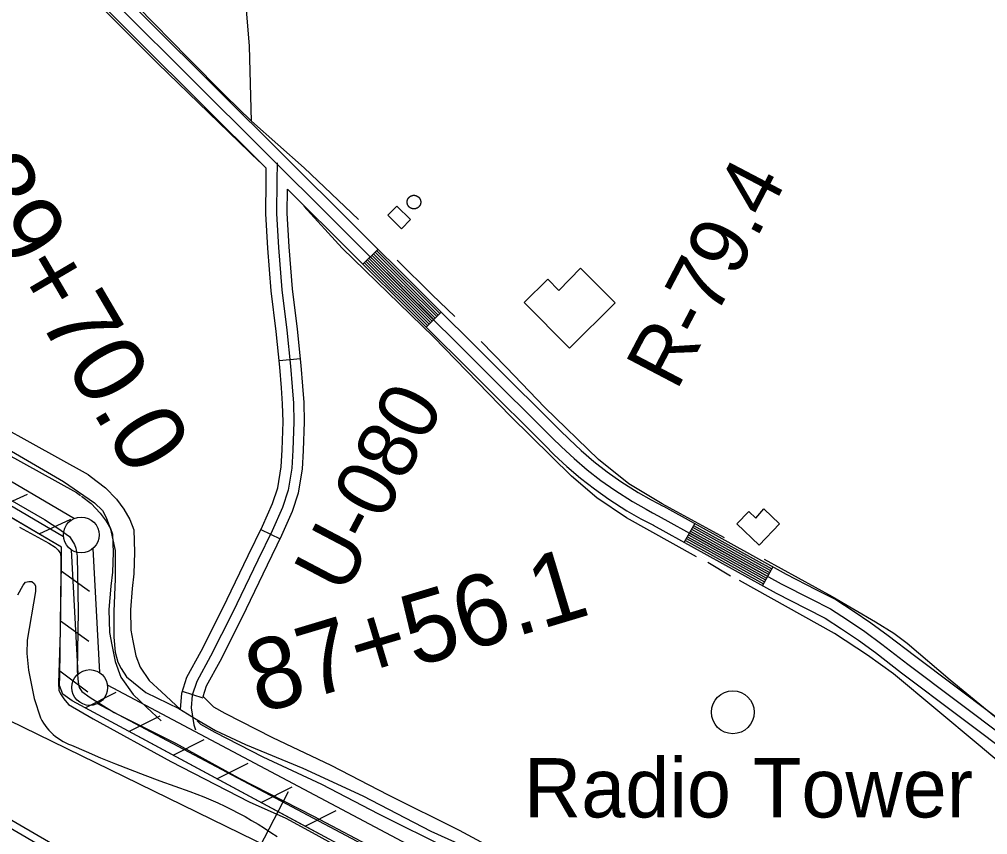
# Model space of a CAD drawing. Extents: x 3715084 to 3753216, y 488173 to 513963.
# Drawn here: x 3720352 to 3721709, y 504207 to 505348 of the extents above; entities that cross this region are included whole.
import ezdxf

# ---------------------------------------------------------------- set-up
doc = ezdxf.new("R2010")
doc.units = 0
for name, color, linetype in [('V-BLDG-OTLN', 7, 'Continuous'), ('V-DOMW-TANK', 7, 'Continuous'), ('V-FLOD-BASE', 7, 'Continuous'), ('V-LEVE-TOET', 7, 'Continuous'), ('V-RIVR-RANG', 7, 'Continuous'), ('V-RIVR-RANG-IDEN', 7, 'Continuous'), ('V-ROAD-CNTR', 7, 'Continuous'), ('V-RRAP-FSHR', 7, 'Continuous'), ('V-SITE-VEGE', 7, 'Continuous'), ('V-SURV-IDEN', 7, 'Continuous'), ('V-SURV-LINE', 7, 'Continuous'), ('V-TOPO-DPTH', 7, 'Continuous'), ('V-TOPO-MINR', 7, 'Continuous'), ('V-TOPO-SHOR', 7, 'Continuous'), ('V-TOPO-TOWR', 7, 'Continuous'), ('V-TOPO-TOWR-IDEN', 7, 'Continuous'), ('V-TOPO-WATR', 7, 'Continuous')]:
    doc.layers.add(name, color=color, linetype=linetype)

msp = doc.modelspace()

# ---------------------------------------------------------------- linework, layer by layer
at = {"layer": 'V-BLDG-OTLN'}
for points in [[(3720880.9, 505086.5), (3720900, 505067.6), (3720887.4, 505054.9), (3720868.4, 505073.7)], [(3721138.3, 504999.6), (3721186.6, 504950.9), (3721122.8, 504887.7), (3721059.4, 504951.7), (3721092.3, 504984.2), (3721107.9, 504968.4)], [(3721395, 504662.5), (3721416.8, 504641.5), (3721388.4, 504612), (3721357.4, 504641.9), (3721374, 504659.1), (3721383.7, 504649.8)]]:
    msp.add_lwpolyline(points, close=True, dxfattribs=at)
at = {"layer": 'V-DOMW-TANK'}
for points in [[(3720896, 505095.7), (3720896.1, 505095.8), (3720896.1, 505096), (3720896.2, 505096.1), (3720896.3, 505096.3), (3720896.3, 505096.4), (3720896.4, 505096.6), (3720896.5, 505096.7), (3720896.6, 505096.9), (3720896.7, 505097), (3720896.7, 505097.2), (3720896.8, 505097.3), (3720896.9, 505097.4), (3720897, 505097.6), (3720897.1, 505097.7), (3720897.2, 505097.8), (3720897.3, 505098), (3720897.4, 505098.1), (3720897.5, 505098.2), (3720897.6, 505098.4), (3720897.7, 505098.5), (3720897.8, 505098.6), (3720898, 505098.7), (3720898.1, 505098.8), (3720898.2, 505099), (3720898.3, 505099.1), (3720898.4, 505099.2), (3720898.6, 505099.3), (3720898.7, 505099.4), (3720898.8, 505099.5), (3720899, 505099.6), (3720899.1, 505099.7), (3720899.2, 505099.8), (3720899.4, 505099.9), (3720899.5, 505100), (3720899.6, 505100.1), (3720899.8, 505100.2), (3720899.9, 505100.3), (3720900.1, 505100.4), (3720900.2, 505100.4), (3720900.3, 505100.5), (3720900.5, 505100.6), (3720900.6, 505100.7), (3720900.8, 505100.8), (3720900.9, 505100.8), (3720901.1, 505100.9), (3720901.2, 505100.9), (3720901.4, 505101), (3720901.6, 505101.1), (3720901.7, 505101.1), (3720901.9, 505101.2), (3720902, 505101.2), (3720902.2, 505101.3), (3720902.3, 505101.3), (3720902.5, 505101.4), (3720902.7, 505101.4), (3720902.8, 505101.4), (3720903, 505101.5), (3720903.2, 505101.5), (3720903.3, 505101.5), (3720903.5, 505101.6), (3720903.7, 505101.6), (3720903.8, 505101.6), (3720904, 505101.6), (3720904.1, 505101.6), (3720904.3, 505101.6), (3720904.5, 505101.6), (3720904.6, 505101.6), (3720904.8, 505101.6), (3720905, 505101.6), (3720905.1, 505101.6), (3720905.3, 505101.6), (3720905.5, 505101.6), (3720905.6, 505101.6), (3720905.8, 505101.6), (3720906, 505101.6), (3720906.1, 505101.6), (3720906.3, 505101.5), (3720906.5, 505101.5), (3720906.6, 505101.5), (3720906.8, 505101.4), (3720907, 505101.4), (3720907.1, 505101.4), (3720907.3, 505101.3), (3720907.4, 505101.3), (3720907.6, 505101.2), (3720907.8, 505101.2), (3720907.9, 505101.1), (3720908.1, 505101.1), (3720908.2, 505101), (3720908.4, 505101), (3720908.5, 505100.9), (3720908.7, 505100.8), (3720908.8, 505100.8), (3720909, 505100.7), (3720909.1, 505100.6), (3720909.3, 505100.5), (3720909.4, 505100.5), (3720909.6, 505100.4), (3720909.7, 505100.3), (3720909.9, 505100.2)], [(3720902.9, 505082.8), (3720902.7, 505082.8), (3720902.5, 505082.9), (3720902.4, 505082.9), (3720902.2, 505083), (3720902.1, 505083), (3720901.9, 505083.1), (3720901.7, 505083.1), (3720901.6, 505083.2), (3720901.4, 505083.2), (3720901.3, 505083.3), (3720901.1, 505083.3), (3720901, 505083.4), (3720900.8, 505083.5), (3720900.7, 505083.6), (3720900.5, 505083.6), (3720900.4, 505083.7), (3720900.2, 505083.8), (3720900.1, 505083.9), (3720899.9, 505084), (3720899.8, 505084), (3720899.6, 505084.1), (3720899.5, 505084.2), (3720899.4, 505084.3), (3720899.2, 505084.4), (3720899.1, 505084.5), (3720899, 505084.6), (3720898.8, 505084.7), (3720898.7, 505084.8), (3720898.6, 505084.9), (3720898.5, 505085), (3720898.3, 505085.1), (3720898.2, 505085.3), (3720898.1, 505085.4), (3720898, 505085.5), (3720897.9, 505085.6), (3720897.8, 505085.7), (3720897.6, 505085.9), (3720897.5, 505086), (3720897.4, 505086.1), (3720897.3, 505086.2), (3720897.2, 505086.4), (3720897.1, 505086.5), (3720897, 505086.6), (3720896.9, 505086.8), (3720896.8, 505086.9), (3720896.8, 505087.1), (3720896.7, 505087.2), (3720896.6, 505087.4), (3720896.5, 505087.5), (3720896.4, 505087.6), (3720896.3, 505087.8), (3720896.3, 505087.9), (3720896.2, 505088.1), (3720896.1, 505088.2), (3720896.1, 505088.4), (3720896, 505088.5), (3720895.9, 505088.7), (3720895.9, 505088.9), (3720895.8, 505089), (3720895.8, 505089.2), (3720895.7, 505089.3), (3720895.7, 505089.5), (3720895.6, 505089.6), (3720895.6, 505089.8), (3720895.5, 505090), (3720895.5, 505090.1), (3720895.5, 505090.3), (3720895.4, 505090.5), (3720895.4, 505090.6), (3720895.4, 505090.8), (3720895.4, 505091), (3720895.4, 505091.1), (3720895.3, 505091.3), (3720895.3, 505091.4), (3720895.3, 505091.6), (3720895.3, 505091.8), (3720895.3, 505091.9), (3720895.3, 505092.1), (3720895.3, 505092.3), (3720895.3, 505092.4), (3720895.3, 505092.6), (3720895.3, 505092.8), (3720895.3, 505092.9), (3720895.4, 505093.1), (3720895.4, 505093.3), (3720895.4, 505093.4), (3720895.4, 505093.6), (3720895.4, 505093.8), (3720895.5, 505093.9), (3720895.5, 505094.1), (3720895.5, 505094.3), (3720895.6, 505094.4), (3720895.6, 505094.6), (3720895.7, 505094.7), (3720895.7, 505094.9), (3720895.8, 505095.1), (3720895.8, 505095.2), (3720895.9, 505095.4), (3720895.9, 505095.5), (3720896, 505095.7)], [(3720914.3, 505091.8), (3720914.3, 505091.6), (3720914.3, 505091.5), (3720914.3, 505091.3), (3720914.3, 505091.1), (3720914.3, 505091), (3720914.3, 505090.8), (3720914.2, 505090.6), (3720914.2, 505090.5), (3720914.2, 505090.3), (3720914.1, 505090.2), (3720914.1, 505090), (3720914.1, 505089.8), (3720914, 505089.7), (3720914, 505089.5), (3720913.9, 505089.4), (3720913.9, 505089.2), (3720913.8, 505089), (3720913.8, 505088.9), (3720913.7, 505088.7), (3720913.7, 505088.6), (3720913.6, 505088.4), (3720913.5, 505088.3), (3720913.5, 505088.1), (3720913.4, 505088), (3720913.3, 505087.8), (3720913.2, 505087.7), (3720913.2, 505087.5), (3720913.1, 505087.4), (3720913, 505087.2), (3720912.9, 505087.1), (3720912.8, 505086.9), (3720912.7, 505086.8), (3720912.6, 505086.7), (3720912.5, 505086.5), (3720912.4, 505086.4), (3720912.3, 505086.3), (3720912.2, 505086.1), (3720912.1, 505086), (3720912, 505085.9), (3720911.9, 505085.8), (3720911.8, 505085.6), (3720911.7, 505085.5), (3720911.6, 505085.4), (3720911.5, 505085.3), (3720911.3, 505085.2), (3720911.2, 505085.1), (3720911.1, 505084.9), (3720911, 505084.8), (3720910.8, 505084.7), (3720910.7, 505084.6), (3720910.6, 505084.5), (3720910.4, 505084.4), (3720910.3, 505084.3), (3720910.2, 505084.2), (3720910, 505084.1), (3720909.9, 505084.1), (3720909.7, 505084), (3720909.6, 505083.9), (3720909.5, 505083.8), (3720909.3, 505083.7), (3720909.2, 505083.6), (3720909, 505083.6), (3720908.9, 505083.5), (3720908.7, 505083.4), (3720908.6, 505083.4), (3720908.4, 505083.3), (3720908.3, 505083.2), (3720908.1, 505083.2), (3720907.9, 505083.1), (3720907.8, 505083.1), (3720907.6, 505083), (3720907.5, 505083), (3720907.3, 505082.9), (3720907.1, 505082.9), (3720907, 505082.8), (3720906.8, 505082.8), (3720906.7, 505082.8), (3720906.5, 505082.7), (3720906.3, 505082.7), (3720906.2, 505082.7), (3720906, 505082.7), (3720905.8, 505082.7), (3720905.7, 505082.6), (3720905.5, 505082.6), (3720905.3, 505082.6), (3720905.2, 505082.6), (3720905, 505082.6), (3720904.8, 505082.6), (3720904.7, 505082.6), (3720904.5, 505082.6), (3720904.3, 505082.6), (3720904.2, 505082.6), (3720904, 505082.6), (3720903.8, 505082.7), (3720903.7, 505082.7), (3720903.5, 505082.7), (3720903.3, 505082.7), (3720903.2, 505082.7), (3720903, 505082.8), (3720902.9, 505082.8)], [(3720909.9, 505100.2), (3720910, 505100.1), (3720910.1, 505100), (3720910.3, 505099.9), (3720910.4, 505099.8), (3720910.5, 505099.7), (3720910.7, 505099.6), (3720910.8, 505099.5), (3720910.9, 505099.4), (3720911.1, 505099.3), (3720911.2, 505099.2), (3720911.3, 505099.1), (3720911.4, 505099), (3720911.6, 505098.9), (3720911.7, 505098.7), (3720911.8, 505098.6), (3720911.9, 505098.5), (3720912, 505098.4), (3720912.1, 505098.3), (3720912.2, 505098.1), (3720912.3, 505098), (3720912.4, 505097.9), (3720912.5, 505097.7), (3720912.6, 505097.6), (3720912.7, 505097.5), (3720912.8, 505097.3), (3720912.9, 505097.2), (3720913, 505097), (3720913.1, 505096.9), (3720913.1, 505096.8), (3720913.2, 505096.6), (3720913.3, 505096.5), (3720913.4, 505096.3), (3720913.5, 505096.2), (3720913.5, 505096), (3720913.6, 505095.9), (3720913.7, 505095.7), (3720913.7, 505095.5), (3720913.8, 505095.4), (3720913.8, 505095.2), (3720913.9, 505095.1), (3720913.9, 505094.9), (3720914, 505094.8), (3720914, 505094.6), (3720914.1, 505094.4), (3720914.1, 505094.3), (3720914.1, 505094.1), (3720914.2, 505094), (3720914.2, 505093.8), (3720914.2, 505093.6), (3720914.3, 505093.5), (3720914.3, 505093.3), (3720914.3, 505093.1), (3720914.3, 505093), (3720914.3, 505092.8), (3720914.3, 505092.6), (3720914.3, 505092.5), (3720914.4, 505092.3), (3720914.4, 505092.1), (3720914.4, 505092), (3720914.3, 505091.8)]]:
    msp.add_lwpolyline(points, dxfattribs=at)
at = {"layer": 'V-FLOD-BASE'}
msp.add_lwpolyline([(3720298.4, 504698.8), (3720387, 504647.6), (3720408.5, 504633.6), (3720417.7, 504627.4), (3720422.3, 504623.9), (3720425.5, 504619), (3720429.3, 504612.7), (3720431.2, 504607.4), (3720433.2, 504596.6), (3720434.2, 504519.3), (3720433.1, 504435.7), (3720434.3, 504419.9), (3720435.8, 504412.7), (3720439.5, 504406.9), (3720451, 504398.5), (3720484.8, 504377.5), (3720570.6, 504334.4), (3720659.1, 504285.9), (3720764.1, 504232.4), (3720856.3, 504184)], dxfattribs=at)
at = {"layer": 'V-LEVE-TOET'}
for points in [[(3720306.7, 504763.1), (3720414, 504701), (3720457.5, 504671.1), (3720468.6, 504660.5), (3720473.7, 504650.6), (3720479.5, 504634), (3720486.3, 504604.3), (3720486.2, 504564.6), (3720484.4, 504518.9), (3720484.6, 504482.8), (3720486.3, 504462), (3720489.8, 504448.1), (3720494.5, 504439.1), (3720501.9, 504427.5), (3720529.4, 504405.5), (3720575.5, 504383.3), (3720599.6, 504368.1), (3720627, 504352.3), (3720669, 504332.8), (3720749.1, 504299.5), (3720833, 504260.9), (3720928.4, 504211.2), (3721018.6, 504171)], [(3720352, 504637), (3720393.1, 504614.8), (3720402.2, 504609.1), (3720406.4, 504604.6), (3720409.6, 504600.2), (3720410.8, 504588), (3720409, 504490.4), (3720406.8, 504418.5), (3720407.4, 504409), (3720409.8, 504403.6), (3720414.4, 504396.5), (3720420.9, 504388.9), (3720455.6, 504368.8), (3720564.3, 504309), (3720673.8, 504252.3), (3720725.3, 504229.8), (3720762.3, 504209.3), (3720849.5, 504161.3)]]:
    msp.add_lwpolyline(points, dxfattribs=at)
at = {"layer": 'V-RIVR-RANG'}
msp.add_line((3720728.8, 504266.5), (3720358.7, 503557.2), dxfattribs=at)
at = {"layer": 'V-ROAD-CNTR'}
for p, q in [((3720854.5, 505026.3), (3720833.3, 505005.1)), ((3720943.1, 504938.2), (3720922, 504916.9)), ((3720715.9, 504870.2), (3720745.8, 504873.1)), ((3721298.2, 504642), (3721283.6, 504615.8)), ((3720690.4, 504633.8), (3720717.4, 504620.7)), ((3721407.5, 504581.5), (3721393, 504555.2)), ((3720580.3, 504407.3), (3720608.9, 504398.1))]:
    msp.add_line(p, q, dxfattribs=at)
for points in [[(3719189.4, 506660.7), (3719987.9, 505866.9), (3721098.7, 504762.3), (3721111.7, 504749.3), (3721129.2, 504733), (3721147.4, 504717.5), (3721166.7, 504702.5), (3721186.3, 504688.6), (3721211, 504672.9), (3721230.2, 504662), (3721239.2, 504657.2), (3721247.2, 504653.1)], [(3719529.4, 506301.6), (3719977.3, 505856.2), (3720697.9, 505139.7)], [(3720145.3, 505731.5), (3721109.3, 504772.9), (3721122.1, 504760.1), (3721139.2, 504744.2), (3721156.9, 504729.1), (3721175.6, 504714.6), (3721194.7, 504701.1), (3721218.8, 504685.7), (3721237.4, 504675.1), (3721246.1, 504670.5), (3721254, 504666.4)], [(3720713.1, 505147.3), (3720712.6, 505121.8), (3720712.3, 505076.2), (3720714.9, 505028.6), (3720719.9, 504969.3), (3720726.9, 504912.6), (3720731.8, 504862.2), (3720734.1, 504833.3), (3720735.9, 504810.6), (3720736.4, 504784.6), (3720735, 504744.8), (3720733.8, 504719.7), (3720728.6, 504688.7), (3720720.7, 504664.7), (3720706.2, 504632.1), (3720686.1, 504590.8), (3720650.5, 504517), (3720620, 504456.3), (3720600.5, 504421), (3720594.3, 504401.9), (3720592.9, 504384.1), (3720596.5, 504360.3), (3720598.8, 504353.4)], [(3720577.7, 504381.5), (3720579.5, 504404.8), (3720586.7, 504427), (3720606.8, 504463.3), (3720637.1, 504523.6), (3720672.6, 504597.3), (3720692.6, 504638.4), (3720706.6, 504670.1), (3720714, 504692.3), (3720718.9, 504721.3), (3720720, 504745.4), (3720721.4, 504784.7), (3720720.9, 504809.9), (3720719.1, 504832.1), (3720716.9, 504860.9), (3720712, 504910.9), (3720705, 504967.8), (3720700, 505027.5), (3720697.3, 505075.8), (3720697.6, 505122), (3720697.9, 505139.7)], [(3720609.4, 504399.8), (3720614.3, 504415), (3720633.3, 504449.3), (3720664, 504510.4), (3720699.6, 504584.3), (3720719.8, 504625.8), (3720734.7, 504659.3), (3720743.2, 504685.1), (3720748.8, 504718.1), (3720750, 504744.2), (3720751.4, 504784.5), (3720750.8, 504811.4), (3720749, 504834.4), (3720746.7, 504863.5), (3720741.8, 504914.2), (3720734.9, 504970.9), (3720729.9, 505029.6), (3720727.3, 505076.6), (3720727.5, 505110.3)], [(3720727.5, 505110.3), (3721088.1, 504751.7), (3721101.3, 504738.5), (3721119.2, 504721.8), (3721138, 504705.8), (3721157.8, 504690.5), (3721177.9, 504676.2), (3721203.3, 504660.1), (3721222.9, 504648.8), (3721232.2, 504643.9), (3721240.3, 504639.7)], [(3720850.3, 505022.1), (3720938.9, 504933.9)], [(3720852.4, 505024.2), (3720941, 504936.1)], [(3720835.5, 505007.2), (3720924.1, 504919)], [(3720837.6, 505009.3), (3720926.2, 504921.2)], [(3720839.7, 505011.4), (3720928.3, 504923.3)], [(3720841.8, 505013.6), (3720930.4, 504925.4)], [(3720843.9, 505015.7), (3720932.6, 504927.6)], [(3720846, 505017.8), (3720934.7, 504929.7)], [(3720848.1, 505019.9), (3720936.8, 504931.8)], [(3720052.4, 504938), (3720245.9, 504822.8), (3720448.5, 504710.8), (3720451.4, 504708.6)], [(3720026.4, 504918.6), (3720230.9, 504796.8), (3720432, 504685.6), (3720437.6, 504681.3)], [(3720451.4, 504708.6), (3720472.6, 504692.3), (3720487.9, 504676.1), (3720498.6, 504662.4), (3720507, 504647.7), (3720512.5, 504633.1), (3720513.5, 504601.8), (3720512.6, 504571.7), (3720510, 504551.3), (3720507.6, 504521.1), (3720508.4, 504492.6), (3720511.1, 504477.7), (3720515.2, 504457), (3720521.1, 504441.1), (3720534.1, 504422.3), (3720551, 504406.5), (3720577.7, 504381.5)], [(3720438.9, 504680.3), (3720452.4, 504670), (3720465.1, 504656.5), (3720473.6, 504645.6), (3720479.7, 504635), (3720482.6, 504627.2), (3720483.5, 504601.7), (3720482.7, 504574.1), (3720480.2, 504554.4), (3720477.5, 504521.9), (3720478.5, 504489.5), (3720481.6, 504472.1), (3720486.3, 504448.7), (3720494.3, 504427.2), (3720511.3, 504402.6), (3720530.5, 504384.6), (3720550.6, 504365.8)], [(3721254.4, 504666.2), (3721426.2, 504571.2), (3721467.9, 504549.8), (3721495.7, 504535.7), (3721520.4, 504519.8), (3721544.9, 504503.1), (3721569.4, 504485.3), (3721606.1, 504457.1), (3722648.1, 503674.3)], [(3721247.2, 504653.1), (3721419.1, 504557.9), (3721461.1, 504536.5), (3721488.2, 504522.7), (3721512.1, 504507.3), (3721536.3, 504490.9), (3721560.4, 504473.3), (3721597, 504445.1), (3722971.8, 503412.3)], [(3721239.9, 504640), (3721412.1, 504544.7), (3721454.3, 504523.1), (3721480.8, 504509.6), (3721503.9, 504494.8), (3721527.6, 504478.6), (3721551.5, 504461.3), (3721587.9, 504433.2), (3722963.1, 503400.1)], [(3721290.9, 504628.9), (3721400.3, 504568.3)], [(3721292.4, 504631.5), (3721401.7, 504571)], [(3721293.8, 504634.1), (3721403.2, 504573.6)], [(3721295.3, 504636.8), (3721404.6, 504576.2)], [(3721296.7, 504639.4), (3721406.1, 504578.8)], [(3721285.1, 504618.4), (3721394.5, 504557.8)], [(3721286.5, 504621), (3721395.9, 504560.5)], [(3721288, 504623.6), (3721397.4, 504563.1)], [(3721289.4, 504626.3), (3721398.8, 504565.7)], [(3720609.4, 504399.8), (3720624.1, 504385.5), (3720640, 504376.5), (3720706.5, 504342.3), (3720788.4, 504304), (3720868.6, 504262.2), (3720968.4, 504213), (3721162.4, 504108.3), (3721455.4, 503950.6), (3721693.3, 503826.5), (3721910.2, 503710.8), (3722158.7, 503578.4), (3722275.3, 503519.1), (3722449.8, 503437.7), (3722572.5, 503385.9), (3722717.5, 503324.9), (3722918.2, 503240.7), (3723155.5, 503141.6), (3723379.3, 503050.7), (3723688.8, 502924.5), (3723919.3, 502828.6)], [(3720601.1, 504366), (3720605.9, 504361.3), (3720625.8, 504350.1), (3720693.3, 504315.4), (3720775.1, 504277.1), (3720855.1, 504235.5), (3720954.6, 504186.4), (3721148.2, 504081.9), (3721441.3, 503924.1), (3721679.3, 503800), (3721896.1, 503684.3), (3722144.8, 503551.8), (3722262.2, 503492.2), (3722437.7, 503410.3), (3722560.8, 503358.3), (3722705.8, 503297.2), (3722906.7, 503213), (3723144.1, 503113.8), (3723368, 503022.9), (3723677.4, 502896.7), (3723907.8, 502800.8)]]:
    msp.add_lwpolyline(points, dxfattribs=at)
at = {"layer": 'V-RRAP-FSHR'}
for p, q in [((3720319.2, 504663.1), (3720363.6, 504683.4)), ((3720379.6, 504627.7), (3720424, 504648)), ((3720410.7, 504575.8), (3720450.3, 504547.2)), ((3720409.8, 504505.8), (3720449.4, 504477.2)), ((3720408.9, 504435.8), (3720448.1, 504406.6)), ((3720444, 504384.2), (3720487.6, 504406.2)), ((3720505.6, 504351.1), (3720549.2, 504373)), ((3720567.3, 504317.9), (3720610.9, 504339.9)), ((3720628.9, 504284.7), (3720672.5, 504306.7)), ((3720690.6, 504251.6), (3720734.2, 504273.5)), ((3720752.2, 504218.4), (3720795.8, 504240.4))]:
    msp.add_line(p, q, dxfattribs=at)
for points in [[(3726789.8, 501978.8), (3725909.9, 502250.2), (3725810, 502279.5), (3725043.4, 502441), (3724981.8, 502452.9), (3724595, 502499.9), (3724237.6, 502584.4), (3723904.7, 502725.9), (3723011.3, 503091.7), (3722299.3, 503386.1), (3720426.2, 504393.8), (3720412.7, 504403.1), (3720408.3, 504415.1), (3720408.7, 504428.5), (3720411.2, 504609.1), (3719265.5, 505280.9), (3719251.6, 505287.3), (3719232.5, 505288), (3719209.2, 505282.4)], [(3723870.2, 502642), (3719362.2, 504842.3), (3719213.6, 504918.2)], [(3720771.9, 504207.8), (3720426.2, 504393.8), (3720412.7, 504403.1), (3720408.3, 504415.1), (3720408.7, 504428.5), (3720411.2, 504609.1), (3720241, 504708.9)]]:
    msp.add_lwpolyline(points, dxfattribs=at)
at = {"layer": 'V-SITE-VEGE'}
for points in [[(3720350, 504542.1), (3720357.3, 504555.6), (3720360.8, 504560.1)], [(3720360.8, 504560.1), (3720365.2, 504561.1), (3720369.3, 504560.8), (3720372.9, 504558.1), (3720374.7, 504555.1), (3720374.4, 504547), (3720362.8, 504479), (3720362.3, 504460.2), (3720364.9, 504436.6), (3720372.8, 504397.1), (3720381.4, 504370), (3720383.4, 504366.3), (3720385.7, 504362.7), (3720388.1, 504359.3), (3720390.7, 504355.9), (3720393.5, 504352.7), (3720396.5, 504349.7), (3720399.6, 504346.8), (3720402.8, 504344.1), (3720406.2, 504341.5), (3720409.8, 504339.1), (3720413.4, 504337), (3720417.1, 504335), (3720421, 504333.2), (3720424.9, 504331.6), (3720445.4, 504322.8), (3720465.9, 504314.2), (3720486.5, 504305.8), (3720507.2, 504297.6), (3720528, 504289.7), (3720548.8, 504281.9), (3720569.8, 504274.3), (3720590.8, 504267), (3720600.7, 504263.2), (3720610.6, 504259.3), (3720620.4, 504255.2), (3720630.2, 504250.9), (3720639.8, 504246.4), (3720649.3, 504241.7), (3720658.8, 504236.8), (3720668.2, 504231.7), (3720677.4, 504226.5), (3720686.6, 504221.1), (3720695.6, 504215.5), (3720704.5, 504209.7), (3720713.3, 504203.7)]]:
    msp.add_lwpolyline(points, dxfattribs=at)
at = {"layer": 'V-SURV-LINE'}
for points in [[(3719281.5, 505324.1), (3720429.1, 504649.2)], [(3720413.9, 504623.3), (3719266.3, 505298.3)], [(3720434.5, 504431.7), (3720424.9, 504605.4)], [(3720454.8, 504607), (3720464.4, 504433.3)], [(3720475.2, 504416.4), (3722364, 503414.7)], [(3722349.9, 503388.2), (3720461.2, 504389.9)]]:
    msp.add_lwpolyline(points, dxfattribs=at)
for centre in [(3720438.7, 504626.1), (3720450.6, 504412.5)]:
    msp.add_circle(centre, 25, dxfattribs=at)
at = {"layer": 'V-TOPO-DPTH'}
msp.add_lwpolyline([(3721745, 503472.4), (3721676.8, 503508), (3721581.9, 503556.3), (3721560.7, 503567), (3721539.5, 503577.6), (3721518.3, 503588.2), (3721497.1, 503598.7), (3721292.5, 503699.7), (3721205.7, 503743.2), (3721119.4, 503787.4), (3721033.5, 503832.7), (3720948.1, 503878.7), (3720797.7, 503961), (3720787.8, 503966.5), (3720777.9, 503972), (3720768.1, 503977.7), (3720758.3, 503983.4), (3720691.6, 504022.5), (3720648.5, 504047.8), (3720605.3, 504073), (3720562.1, 504098.2), (3720518.9, 504123.3), (3720034, 504404.7)], dxfattribs=at)
at = {"layer": 'V-TOPO-MINR'}
msp.add_lwpolyline([(3720380.5, 504191.2), (3720020.8, 504401.1)], dxfattribs=at)
at = {"layer": 'V-TOPO-SHOR'}
msp.add_line((3721348.5, 504568.2), (3721316.8, 504587.7), dxfattribs=at)
for points in [[(3720827.1, 505067.9), (3720750.9, 505139.9), (3720677.4, 505205.4), (3720640.5, 505241.2), (3720588.2, 505294.2), (3720517.3, 505366), (3720453.6, 505427.3), (3720382.7, 505498.2), (3720308.6, 505571.3), (3720229.9, 505649.2), (3720185.8, 505694.7)], [(3720688.4, 505148.7), (3720546, 505286.3), (3720386.8, 505446.4), (3720223.4, 505605.5)], [(3720677.4, 505205.4), (3720674.5, 505310.6), (3720665.2, 505423.7)], [(3721300.6, 504595.4), (3721202.7, 504650), (3721161.2, 504678.1), (3721125.6, 504708.4), (3721040.8, 504791.8), (3720932.2, 504903.3), (3720804.1, 505027.4), (3720750.5, 505086.3)], [(3720961.9, 504932), (3720930.5, 504962.2), (3720881.4, 505010.7)], [(3721340, 504622), (3721252.8, 504669.9), (3721205.9, 504697.5), (3721163.3, 504731.9), (3721088.3, 504804.6), (3721034.1, 504861.1), (3720999.1, 504897)], [(3721395.6, 504592.4), (3721490.8, 504540.1), (3721551.7, 504504.7), (3721577, 504488.7), (3721596, 504474.8), (3721656.3, 504423.3), (3721754.7, 504342.6), (3721900.2, 504218.7), (3721952.8, 504176), (3722025.8, 504116.3), (3722109.6, 504048.7), (3722191, 503988.7), (3722315, 503900.1), (3722405, 503835.3), (3722499.9, 503768.9), (3722613, 503686.3), (3722652.8, 503658.5)], [(3721816.3, 504231.1), (3721695.4, 504332.5), (3721576.5, 504431.6), (3721540.1, 504458), (3721494, 504488.1), (3721405.5, 504537.6), (3721361, 504562.3)]]:
    msp.add_lwpolyline(points, dxfattribs=at)
at = {"layer": 'V-TOPO-TOWR'}
msp.add_circle((3721351.5, 504377.8), 30, dxfattribs=at)
at = {"layer": 'V-TOPO-WATR'}
msp.add_lwpolyline([(3721745, 503472.4), (3721676.8, 503508), (3721581.9, 503556.3), (3721560.7, 503567), (3721539.5, 503577.6), (3721518.3, 503588.2), (3721497.1, 503598.7), (3721292.5, 503699.7), (3721205.7, 503743.2), (3721119.4, 503787.4), (3721033.5, 503832.7), (3720948.1, 503878.7), (3720797.7, 503961), (3720787.8, 503966.5), (3720777.9, 503972), (3720768.1, 503977.7), (3720758.3, 503983.4), (3720691.6, 504022.5), (3720648.5, 504047.8), (3720605.3, 504073), (3720562.1, 504098.2), (3720518.9, 504123.3), (3720034, 504404.7)], dxfattribs=at)

# ---------------------------------------------------------------- texts
at = {"layer": 'V-RIVR-RANG-IDEN'}
for s, rotation, p in [('R-79.4', 62.323, (3721272.6, 504826.4)), ('U-080', 62.3023, (3720807.2, 504540.3))]:
    msp.add_text(s, height=83, rotation=rotation, dxfattribs=at).set_placement(p)
at = {"layer": 'V-SURV-IDEN'}
for s, rotation, p in [('89+70.0', 300.4272, (3720263.1, 505124.2)), ('87+56.1', 16.7484, (3720688.3, 504375.2))]:
    msp.add_text(s, height=100, rotation=rotation, dxfattribs=at).set_placement(p)
at = {"layer": 'V-TOPO-TOWR-IDEN'}
msp.add_text('Radio Tower', height=83, dxfattribs=at).set_placement((3721059, 504230.6))

doc.saveas('drawing.dxf')
